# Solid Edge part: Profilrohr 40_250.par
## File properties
Username: ahadarics
Dokumentum tartalom típus: 0
Author: ahadarics
Last saved by: ahadarics
Revision: 86
Sűrűség: 0,000 kg/m^3
Pontosság: 0,990
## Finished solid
Body 1: solid body, 175 faces, 519 edges, 346 vertices.
  Faces by surface: cylinder 107, plane 68
  Edges by curve: line 305, circle 214
Bounding box of the edges (mm): 51.354 x 51.354 x 293.000, from (-25.6768, -25.6768, -184) to (25.6768, 25.6768, 109).
Cylindrical faces by radius (mm): R0.1 x16, R0.2 x30, R0.5 x28, R1 x8, R2.7 x8, R3.5 x4, R5 x4, R20 x1, R22 x8
Planar faces by outward normal: +x 6, +y 6, +z 1, -x 4, -y 4, -z 1, oblique 46
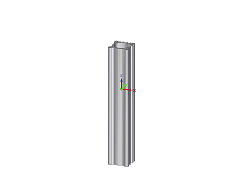
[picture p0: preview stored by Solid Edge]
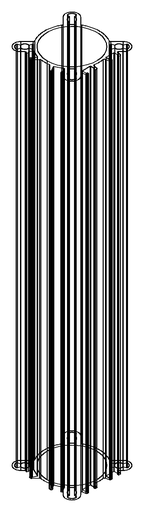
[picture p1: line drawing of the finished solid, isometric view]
